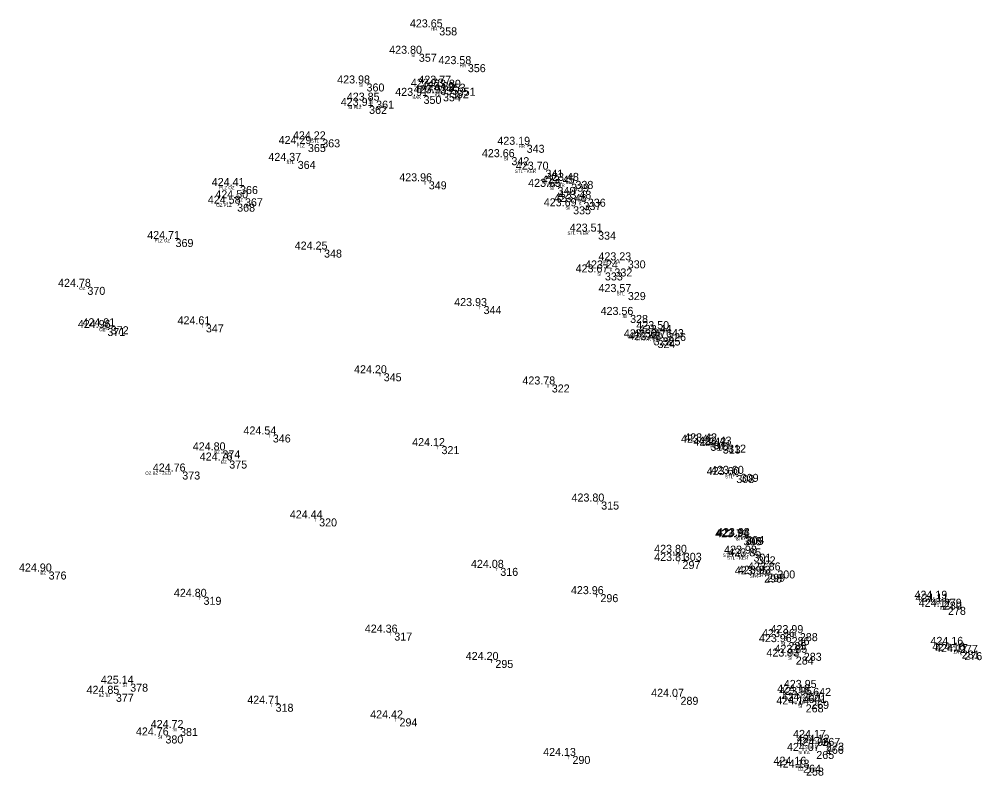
# Model space of a CAD drawing. Extents: x -639373 to -639057, y -1138651 to -1138359.
# Drawn here: x -639327.9 to -639237.7, y -1138429.7 to -1138358.9 of the extents above; entities that cross this region are included whole.
import ezdxf

# ---------------------------------------------------------------- set-up
doc = ezdxf.new("R2010")
doc.units = 0
for name, color, linetype in [('Vrstva 11', 7, 'Continuous'), ('Vrstva 12', 7, 'Continuous'), ('Vrstva 13', 7, 'Continuous'), ('Vrstva 14', 7, 'Continuous'), ('Vrstva 57', 7, 'Continuous')]:
    doc.layers.add(name, color=color, linetype=linetype)

msp = doc.modelspace()

# ---------------------------------------------------------------- linework, layer by layer
at = {"layer": 'Vrstva 11'}
for p, q in [((-639288.83, -1138359.67), (-639288.83, -1138359.67)), ((-639290.74, -1138362.14), (-639290.74, -1138362.14)), ((-639286.15, -1138363.11), (-639286.15, -1138363.11)), ((-639295.64, -1138364.92), (-639295.64, -1138364.92)), ((-639288.04, -1138364.94), (-639288.04, -1138364.94)), ((-639288.74, -1138365.22), (-639288.74, -1138365.22)), ((-639288.48, -1138365.84), (-639288.48, -1138365.84)), ((-639287.74, -1138365.55), (-639287.74, -1138365.55)), ((-639287.1, -1138365.32), (-639287.1, -1138365.32)), ((-639294.74, -1138366.53), (-639294.74, -1138366.53)), ((-639290.3, -1138366.08), (-639290.3, -1138366.08)), ((-639295.4, -1138367.02), (-639295.4, -1138367.02)), ((-639299.79, -1138370.15), (-639299.79, -1138370.15)), ((-639301.13, -1138370.59), (-639301.13, -1138370.59)), ((-639280.64, -1138370.66), (-639280.64, -1138370.66)), ((-639302.09, -1138372.17), (-639302.09, -1138372.17)), ((-639282.07, -1138371.82), (-639282.07, -1138371.82)), ((-639278.88, -1138372.99), (-639278.88, -1138372.99)), ((-639307.49, -1138374.52), (-639307.49, -1138374.52)), ((-639289.81, -1138374.08), (-639289.81, -1138374.08)), ((-639277.75, -1138374.6), (-639277.75, -1138374.6)), ((-639276.47, -1138374.3), (-639276.47, -1138374.3)), ((-639276.07, -1138374.04), (-639276.07, -1138374.04)), ((-639307.03, -1138375.67), (-639307.03, -1138375.67)), ((-639274.91, -1138375.71), (-639274.91, -1138375.71)), ((-639307.76, -1138376.17), (-639307.76, -1138376.17)), ((-639276.29, -1138376.42), (-639276.29, -1138376.42)), ((-639275.32, -1138376.02), (-639275.32, -1138376.02)), ((-639273.95, -1138378.79), (-639273.95, -1138378.79)), ((-639313.53, -1138379.48), (-639313.53, -1138379.48)), ((-639299.62, -1138380.47), (-639299.62, -1138380.47)), ((-639271.17, -1138381.48), (-639271.17, -1138381.48)), ((-639273.31, -1138382.61), (-639273.31, -1138382.61)), ((-639272.42, -1138382.24), (-639272.42, -1138382.24)), ((-639321.79, -1138383.96), (-639321.79, -1138383.96)), ((-639271.16, -1138384.45), (-639271.16, -1138384.45)), ((-639284.68, -1138385.76), (-639284.68, -1138385.76)), ((-639270.95, -1138386.59), (-639270.95, -1138386.59)), ((-639310.69, -1138387.47), (-639310.69, -1138387.47)), ((-639319.92, -1138387.81), (-639319.92, -1138387.81)), ((-639319.6, -1138387.65), (-639319.6, -1138387.65)), ((-639267.59, -1138387.92), (-639267.59, -1138387.92)), ((-639267.39, -1138388.28), (-639267.39, -1138388.28)), ((-639268.76, -1138388.69), (-639268.76, -1138388.69)), ((-639268.38, -1138388.94), (-639268.38, -1138388.94)), ((-639267.91, -1138388.7), (-639267.91, -1138388.7)), ((-639294.03, -1138392.05), (-639294.03, -1138392.05)), ((-639278.29, -1138393.1), (-639278.29, -1138393.1)), ((-639304.42, -1138397.78), (-639304.42, -1138397.78)), ((-639309.14, -1138399.27), (-639309.14, -1138399.27)), ((-639288.62, -1138398.87), (-639288.62, -1138398.87)), ((-639263.43, -1138398.56), (-639263.43, -1138398.56)), ((-639263.13, -1138398.43), (-639263.13, -1138398.43)), ((-639262.27, -1138398.82), (-639262.27, -1138398.82)), ((-639261.77, -1138398.73), (-639261.77, -1138398.73)), ((-639308.5, -1138400.22), (-639308.5, -1138400.22)), ((-639312.9, -1138401.25), (-639312.9, -1138401.25)), ((-639261, -1138401.58), (-639261, -1138401.58)), ((-639260.59, -1138401.47), (-639260.59, -1138401.47)), ((-639273.66, -1138404.06), (-639273.66, -1138404.06)), ((-639300.08, -1138405.64), (-639300.08, -1138405.64)), ((-639260.14, -1138407.37), (-639260.14, -1138407.37)), ((-639260.06, -1138407.29), (-639260.06, -1138407.29)), ((-639260.33, -1138407.41), (-639260.33, -1138407.41)), ((-639265.92, -1138408.86), (-639265.92, -1138408.86)), ((-639259.4, -1138408.94), (-639259.4, -1138408.94)), ((-639259, -1138409.19), (-639259, -1138409.19)), ((-639266.04, -1138409.63), (-639266.04, -1138409.63)), ((-639325.42, -1138410.61), (-639325.42, -1138410.61)), ((-639283.11, -1138410.27), (-639283.11, -1138410.27)), ((-639258.39, -1138410.89), (-639258.39, -1138410.89)), ((-639258.11, -1138410.82), (-639258.11, -1138410.82)), ((-639257.16, -1138410.51), (-639257.16, -1138410.51)), ((-639273.73, -1138412.73), (-639273.73, -1138412.73)), ((-639310.91, -1138412.98), (-639310.91, -1138412.98)), ((-639241.56, -1138413.16), (-639241.56, -1138413.16)), ((-639241.56, -1138413.43), (-639241.56, -1138413.43)), ((-639241.17, -1138413.92), (-639241.17, -1138413.92)), ((-639293.04, -1138416.33), (-639293.04, -1138416.33)), ((-639255.05, -1138416.38), (-639255.05, -1138416.38)), ((-639256.12, -1138417.22), (-639256.12, -1138417.22)), ((-639255.82, -1138416.75), (-639255.82, -1138416.75)), ((-639240.05, -1138417.48), (-639240.05, -1138417.48)), ((-639239.88, -1138418.01), (-639239.88, -1138418.01)), ((-639239.64, -1138418.16), (-639239.64, -1138418.16)), ((-639283.57, -1138418.89), (-639283.57, -1138418.89)), ((-639255.43, -1138418.57), (-639255.43, -1138418.57)), ((-639254.68, -1138418.22), (-639254.68, -1138418.22)), ((-639317.78, -1138421.11), (-639317.78, -1138421.11)), ((-639253.8, -1138421.51), (-639253.8, -1138421.51)), ((-639319.12, -1138422.06), (-639319.12, -1138422.06)), ((-639266.23, -1138422.34), (-639266.23, -1138422.34)), ((-639254.42, -1138421.94), (-639254.42, -1138421.94)), ((-639254.24, -1138422.17), (-639254.24, -1138422.17)), ((-639253.99, -1138422.72), (-639253.99, -1138422.72)), ((-639304.16, -1138422.99), (-639304.16, -1138422.99)), ((-639254.5, -1138423.05), (-639254.5, -1138423.05)), ((-639292.55, -1138424.36), (-639292.55, -1138424.36)), ((-639313.11, -1138425.26), (-639313.11, -1138425.26)), ((-639314.48, -1138425.96), (-639314.48, -1138425.96)), ((-639252.94, -1138426.19), (-639252.94, -1138426.19)), ((-639252.61, -1138426.93), (-639252.61, -1138426.93)), ((-639252.59, -1138426.63), (-639252.59, -1138426.63)), ((-639276.35, -1138427.88), (-639276.35, -1138427.88)), ((-639253.51, -1138427.41), (-639253.51, -1138427.41)), ((-639254.75, -1138428.7), (-639254.75, -1138428.7)), ((-639254.47, -1138428.97), (-639254.47, -1138428.97))]:
    msp.add_line(p, q, dxfattribs=at)

# ---------------------------------------------------------------- texts
at = {"layer": 'Vrstva 12'}
for s, p in [('423.65 ', (-639291.3, -1138359.67)), ('423.98 ', (-639298.109, -1138364.92)), ('423.85 ', (-639297.21, -1138366.53)), ('423.91 ', (-639292.675, -1138366.08)), ('423.91 ', (-639297.775, -1138367.02)), ('424.22 ', (-639302.259, -1138370.15)), ('424.29 ', (-639303.599, -1138370.59)), ('424.37 ', (-639304.559, -1138372.17)), ('424.41 ', (-639309.865, -1138374.52)), ('423.45 ', (-639278.94, -1138374.3)), ('423.48 ', (-639278.539, -1138374.04)), ('424.50 ', (-639309.529, -1138375.67)), ('423.46 ', (-639277.806, -1138376.02)), ('423.48 ', (-639277.379, -1138375.71)), ('424.71 ', (-639315.905, -1138379.48)), ('423.23 ', (-639273.639, -1138381.48)), ('423.24 ', (-639274.889, -1138382.24)), ('424.78 ', (-639324.259, -1138383.96)), ('424.96 ', (-639322.406, -1138387.81)), ('424.91 ', (-639321.975, -1138387.65)), ('423.50 ', (-639270.089, -1138387.92)), ('423.44 ', (-639269.859, -1138388.28)), ('423.50 ', (-639271.259, -1138388.69)), ('423.48 ', (-639270.849, -1138388.94)), ('423.47 ', (-639270.379, -1138388.7)), ('423.42 ', (-639264.739, -1138398.82)), ('423.43 ', (-639264.239, -1138398.73)), ('424.76 ', (-639315.386, -1138401.25)), ('423.60 ', (-639263.089, -1138401.47)), ('423.80 ', (-639268.419, -1138408.86)), ('424.90 ', (-639327.919, -1138410.61)), ('423.86 ', (-639259.646, -1138410.51)), ('424.19 ', (-639244.029, -1138413.16)), ('424.11 ', (-639243.935, -1138413.43)), ('424.17 ', (-639243.639, -1138413.92)), ('423.99 ', (-639257.519, -1138416.38)), ('424.16 ', (-639242.536, -1138417.48)), ('424.16 ', (-639242.366, -1138418.01)), ('423.85 ', (-639257.15, -1138418.22)), ('424.17 ', (-639242.109, -1138418.16)), ('425.14 ', (-639320.249, -1138421.11)), ('423.95 ', (-639256.27, -1138421.51)), ('424.85 ', (-639321.59, -1138422.06)), ('424.19 ', (-639256.889, -1138421.94)), ('423.95 ', (-639256.71, -1138422.17)), ('424.72 ', (-639315.579, -1138425.26)), ('424.76 ', (-639316.966, -1138425.96)), ('424.06 ', (-639255.096, -1138426.93)), ('424.12 ', (-639255.059, -1138426.63)), ('424.07 ', (-639255.979, -1138427.41)), ('424.13 ', (-639256.939, -1138428.97))]:
    msp.add_text(s, height=0.75, dxfattribs=at).set_placement(p)
at = {"layer": 'Vrstva 13'}
for s, p in [(' 358', (-639288.83, -1138360.42)), (' 357', (-639290.74, -1138362.89)), (' 356', (-639286.15, -1138363.86)), (' 360', (-639295.64, -1138365.67)), (' 353', (-639288.04, -1138365.69)), (' 355', (-639288.74, -1138365.97)), (' 354', (-639288.48, -1138366.59)), (' 352', (-639287.74, -1138366.3)), (' 351', (-639287.1, -1138366.07)), (' 361', (-639294.74, -1138367.28)), (' 350', (-639290.3, -1138366.83)), (' 362', (-639295.4, -1138367.77)), (' 363', (-639299.79, -1138370.9)), (' 365', (-639301.13, -1138371.34)), (' 343', (-639280.64, -1138371.41)), (' 364', (-639302.09, -1138372.92)), (' 342', (-639282.07, -1138372.57)), (' 341', (-639278.88, -1138373.74)), (' 338', (-639276.07, -1138374.79)), (' 366', (-639307.49, -1138375.27)), (' 349', (-639289.81, -1138374.83)), (' 340', (-639277.75, -1138375.35)), (' 339', (-639276.47, -1138375.05)), (' 367', (-639307.03, -1138376.42)), (' 336', (-639274.91, -1138376.46)), (' 368', (-639307.76, -1138376.92)), (' 335', (-639276.29, -1138377.17)), (' 337', (-639275.32, -1138376.77)), (' 334', (-639273.95, -1138379.54)), (' 369', (-639313.53, -1138380.23)), (' 348', (-639299.62, -1138381.22)), (' 330', (-639271.17, -1138382.23)), (' 333', (-639273.31, -1138383.36)), (' 332', (-639272.42, -1138382.99)), (' 370', (-639321.79, -1138384.71)), (' 329', (-639271.16, -1138385.2)), (' 344', (-639284.68, -1138386.51)), (' 328', (-639270.95, -1138387.34)), (' 347', (-639310.69, -1138388.22)), (' 371', (-639319.92, -1138388.56)), (' 372', (-639319.6, -1138388.4)), (' 643', (-639267.59, -1138388.67)), (' 326', (-639267.39, -1138389.03)), (' 323', (-639268.76, -1138389.44)), (' 324', (-639268.38, -1138389.69)), (' 325', (-639267.91, -1138389.45)), (' 345', (-639294.03, -1138392.8)), (' 322', (-639278.29, -1138393.85)), (' 346', (-639304.42, -1138398.53)), (' 374', (-639309.14, -1138400.02)), (' 321', (-639288.62, -1138399.62)), (' 310', (-639263.43, -1138399.31)), (' 311', (-639263.13, -1138399.18)), (' 313', (-639262.27, -1138399.57)), (' 312', (-639261.77, -1138399.48)), (' 375', (-639308.5, -1138400.97)), (' 373', (-639312.9, -1138402)), (' 308', (-639261, -1138402.33)), (' 309', (-639260.59, -1138402.22)), (' 315', (-639273.66, -1138404.81)), (' 320', (-639300.08, -1138406.39)), (' 305', (-639260.14, -1138408.12)), (' 304', (-639260.06, -1138408.04)), (' 306', (-639260.33, -1138408.16)), (' 303', (-639265.92, -1138409.61)), (' 301', (-639259.4, -1138409.69)), (' 302', (-639259, -1138409.94)), (' 297', (-639266.04, -1138410.38)), (' 376', (-639325.42, -1138411.36)), (' 316', (-639283.11, -1138411.02)), (' 298', (-639258.39, -1138411.64)), (' 299', (-639258.11, -1138411.57)), (' 300', (-639257.16, -1138411.26)), (' 296', (-639273.73, -1138413.48)), (' 319', (-639310.91, -1138413.73)), (' 279', (-639241.56, -1138413.91)), (' 280', (-639241.56, -1138414.18)), (' 278', (-639241.17, -1138414.67)), (' 317', (-639293.04, -1138417.08)), (' 288', (-639255.05, -1138417.13)), (' 285', (-639256.12, -1138417.97)), (' 286', (-639255.82, -1138417.5)), (' 283', (-639254.68, -1138418.97)), (' 277', (-639240.05, -1138418.23)), (' 281', (-639239.88, -1138418.76)), (' 276', (-639239.64, -1138418.91)), (' 295', (-639283.57, -1138419.64)), (' 284', (-639255.43, -1138419.32)), (' 378', (-639317.78, -1138421.86)), (' 642', (-639253.8, -1138422.26)), (' 377', (-639319.12, -1138422.81)), (' 289', (-639266.23, -1138423.09)), (' 270', (-639254.42, -1138422.69)), (' 641', (-639254.24, -1138422.92)), (' 269', (-639253.99, -1138423.47)), (' 318', (-639304.16, -1138423.74)), (' 268', (-639254.5, -1138423.8)), (' 294', (-639292.55, -1138425.11)), (' 381', (-639313.11, -1138426.01)), (' 380', (-639314.48, -1138426.71)), (' 267', (-639252.94, -1138426.94)), (' 266', (-639252.61, -1138427.68)), (' 273', (-639252.59, -1138427.38)), (' 290', (-639276.35, -1138428.63)), (' 265', (-639253.51, -1138428.16)), (' 264', (-639254.75, -1138429.45)), (' 258', (-639254.47, -1138429.72))]:
    msp.add_text(s, height=0.75, dxfattribs=at).set_placement(p)
at = {"layer": 'Vrstva 14'}
for s, p in [('423.80 ', (-639293.239, -1138362.14)), ('423.58 ', (-639288.619, -1138363.11)), ('423.73 ', (-639291.209, -1138365.22)), ('423.77 ', (-639290.509, -1138364.94)), ('423.82 ', (-639290.209, -1138365.55)), ('423.80 ', (-639289.599, -1138365.32)), ('423.93 ', (-639290.949, -1138365.84)), ('423.19 ', (-639283.109, -1138370.66)), ('423.66 ', (-639284.556, -1138371.82)), ('423.70 ', (-639281.379, -1138372.99)), ('423.96 ', (-639292.296, -1138374.08)), ('423.65 ', (-639280.22, -1138374.6)), ('424.58 ', (-639310.229, -1138376.17)), ('423.69 ', (-639278.759, -1138376.42)), ('423.51 ', (-639276.325, -1138378.79)), ('424.25 ', (-639302.09, -1138380.47)), ('423.67 ', (-639275.779, -1138382.61)), ('423.57 ', (-639273.629, -1138384.45)), ('423.93 ', (-639287.149, -1138385.76)), ('423.56 ', (-639273.436, -1138386.59)), ('424.61 ', (-639313.065, -1138387.47)), ('424.20 ', (-639296.529, -1138392.05)), ('423.78 ', (-639280.759, -1138393.1)), ('424.54 ', (-639306.889, -1138397.78)), ('424.12 ', (-639291.089, -1138398.87)), ('423.45 ', (-639265.9, -1138398.56)), ('423.42 ', (-639265.599, -1138398.43)), ('424.80 ', (-639311.639, -1138399.27)), ('424.76 ', (-639310.986, -1138400.22)), ('423.60 ', (-639263.499, -1138401.58)), ('423.80 ', (-639276.159, -1138404.06)), ('424.44 ', (-639302.549, -1138405.64)), ('423.71 ', (-639262.705, -1138407.41)), ('423.94 ', (-639262.609, -1138407.37)), ('423.93 ', (-639262.529, -1138407.29)), ('423.98 ', (-639261.869, -1138408.94)), ('423.81 ', (-639268.415, -1138409.63)), ('423.85 ', (-639261.47, -1138409.19)), ('424.08 ', (-639285.579, -1138410.27)), ('423.93 ', (-639260.579, -1138410.82)), ('423.95 ', (-639260.86, -1138410.89)), ('424.80 ', (-639313.409, -1138412.98)), ('423.96 ', (-639276.216, -1138412.73)), ('424.36 ', (-639295.526, -1138416.33)), ('423.96 ', (-639258.306, -1138416.75)), ('423.96 ', (-639258.606, -1138417.22)), ('424.20 ', (-639286.069, -1138418.89)), ('423.93 ', (-639257.899, -1138418.57)), ('424.07 ', (-639268.699, -1138422.34)), ('424.71 ', (-639306.535, -1138422.99)), ('424.14 ', (-639256.969, -1138423.05)), ('424.20 ', (-639256.489, -1138422.72)), ('424.42 ', (-639295.019, -1138424.36)), ('424.17 ', (-639255.409, -1138426.19)), ('424.13 ', (-639278.819, -1138427.88)), ('424.16 ', (-639257.236, -1138428.7))]:
    msp.add_text(s, height=0.75, dxfattribs=at).set_placement(p)
at = {"layer": 'Vrstva 57'}
for s, p in [('HR', (-639289.319, -1138359.97)), ('SI', (-639291.178, -1138362.44)), ('HR', (-639286.639, -1138363.41)), ('SI', (-639296.078, -1138365.22)), ('K', (-639288.215, -1138365.24)), ('K KA SI', (-639290.678, -1138365.52)), ('SI K KA', (-639289.74, -1138365.85)), ('KA', (-639288.98, -1138366.14)), ('SI', (-639287.538, -1138365.62)), ('SI', (-639295.178, -1138366.83)), ('SAK', (-639291.075, -1138366.38)), ('SI PLZ', (-639297.089, -1138367.32)), ('STL', (-639300.565, -1138370.45)), ('PLZ', (-639301.919, -1138370.89)), ('HR', (-639281.129, -1138370.96)), ('STL', (-639302.865, -1138372.47)), ('SI', (-639282.508, -1138372.12)), ('STL - KER', (-639281.469, -1138373.29)), ('PLZ OZ', (-639309.179, -1138374.82)), ('T', (-639290.01, -1138374.38)), ('KA K HR', (-639278.459, -1138374.6)), ('SI', (-639278.188, -1138374.9)), ('KA', (-639276.57, -1138374.34)), ('OZ', (-639307.519, -1138375.97)), ('KA', (-639275.41, -1138376.01)), ('OZ PLZ', (-639309.449, -1138376.47)), ('SI', (-639276.728, -1138376.72)), ('K', (-639275.495, -1138376.32)), ('STL - KER', (-639276.539, -1138379.09)), ('PLZ OZ', (-639315.219, -1138379.78)), ('T', (-639299.82, -1138380.77)), ('PL K KA', (-639273.17, -1138381.78)), ('SI', (-639273.748, -1138382.91)), ('K', (-639272.595, -1138382.54)), ('OZ', (-639322.279, -1138384.26)), ('STL', (-639271.935, -1138384.75)), ('T', (-639284.88, -1138386.06)), ('SI', (-639271.388, -1138386.89)), ('T', (-639310.89, -1138387.77)), ('OZ', (-639320.409, -1138388.11)), ('OZ', (-639320.089, -1138387.95)), ('K PL', (-639268.665, -1138388.22)), ('K PL', (-639268.465, -1138388.58)), ('SI KA', (-639270.16, -1138388.99)), ('K CH', (-639268.985, -1138389)), ('K', (-639268.555, -1138389.24)), ('T', (-639294.23, -1138392.35)), ('T', (-639278.49, -1138393.4)), ('T', (-639304.62, -1138398.08)), ('BZ', (-639309.629, -1138399.57)), ('T', (-639288.82, -1138399.17)), ('SI', (-639263.868, -1138398.86)), ('K', (-639263.305, -1138398.73)), ('PL CH', (-639263.145, -1138399.03)), ('CH', (-639262.745, -1138399.12)), ('BZ', (-639308.989, -1138400.52)), ('OZ BZ - ZED', (-639316.091, -1138401.55)), ('STL', (-639261.775, -1138401.88)), ('PL', (-639261.065, -1138401.77)), ('T', (-639273.86, -1138404.36)), ('T', (-639300.28, -1138405.94)), ('STL', (-639260.835, -1138407.59)), ('K', (-639260.315, -1138407.67)), ('SI', (-639260.768, -1138407.71)), ('SAK', (-639266.695, -1138409.16)), ('STL - KER', (-639261.989, -1138409.24)), ('STL - KER', (-639261.589, -1138409.49)), ('T', (-639266.24, -1138409.93)), ('BZ', (-639325.909, -1138410.91)), ('T', (-639283.31, -1138410.57)), ('SI K', (-639259.465, -1138411.19)), ('K CH', (-639259.185, -1138411.12)), ('CH PL', (-639258.535, -1138410.81)), ('T', (-639273.93, -1138413.03)), ('T', (-639311.11, -1138413.28)), ('KB KC', (-639242.949, -1138413.46)), ('ZAA', (-639242.36, -1138413.73)), ('KB', (-639241.659, -1138414.22)), ('T', (-639293.24, -1138416.63)), ('PL', (-639255.525, -1138416.68)), ('SI', (-639256.558, -1138417.52)), ('SI', (-639256.258, -1138417.05)), ('PL SI', (-639256.018, -1138418.52)), ('K KA', (-639241.15, -1138417.78)), ('ZA', (-639240.38, -1138418.31)), ('K', (-639239.815, -1138418.46)), ('T', (-639283.77, -1138419.19)), ('SI', (-639255.868, -1138418.87)), ('SI', (-639318.218, -1138421.41)), ('PL K', (-639254.875, -1138421.81)), ('BZ SI', (-639320.458, -1138422.36)), ('T', (-639266.43, -1138422.64)), ('SI KC', (-639255.809, -1138422.24)), ('SI KB', (-639255.379, -1138423.02)), ('ZA', (-639254.74, -1138422.47)), ('T', (-639304.36, -1138423.29)), ('SI', (-639254.938, -1138423.35)), ('T', (-639292.75, -1138424.66)), ('SI', (-639313.548, -1138425.56)), ('SI', (-639314.918, -1138426.26)), ('SI KA', (-639254.34, -1138426.49)), ('SI K K', (-639254.285, -1138427.23)), ('ZA', (-639253.09, -1138426.93)), ('T', (-639276.55, -1138428.18)), ('SI KA', (-639254.91, -1138427.71)), ('SI', (-639255.188, -1138429)), ('DZ', (-639254.959, -1138429.27))]:
    msp.add_text(s, height=0.3, dxfattribs=at).set_placement(p)

doc.saveas('drawing.dxf')
